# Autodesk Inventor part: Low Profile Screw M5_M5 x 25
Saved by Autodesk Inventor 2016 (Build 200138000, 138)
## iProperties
Created: 2015-11
Part Number: Low Profile Screw M5_M5 x 25
Material: Generic
Document SubType Name: Modeling
Designer: John
Density: 1 g/cm^3
Appearance: Default
Author: John
Revision Number: ANY
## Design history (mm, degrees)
feature "Cut-Extrude2"
body "Solid1"
